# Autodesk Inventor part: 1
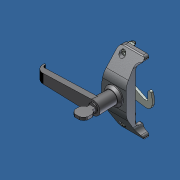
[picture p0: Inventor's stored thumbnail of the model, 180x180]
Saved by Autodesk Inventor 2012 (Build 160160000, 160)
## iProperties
Created: 2014-06
Part Number: 1
Material: Default
Document SubType Name: Modeling
Designer: Admin
Density: 1 g/cm^3
Mass: 101.851 g
Surface Area: 376.252 cm^2
Volume: 101.851 cm^3
Translation Standard: STEP AP214IS
FileName: 21_0959_0_1.stp
PreProcessor: ACIS
PostProcessor: Build: 160, Release: 2012 RTM - Date: Tue 03/01/2011
Sent Units: millimeter
Uncertainty: 1e-06
Author: Admin
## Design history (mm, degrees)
feature "Base1"
body "Solid1"
